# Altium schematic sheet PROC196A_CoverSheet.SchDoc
size 431 x 279 mm; Date: Not shown in title block; ApprovedBy: Not shown in title block; CheckedBy: Not shown in title block; Author: Not shown in title block; CompanyName: Not shown in title block; Engineer: Not shown in title block; Organization: Not shown in title block; Address1: Not shown in title block; Address2: Not shown in title block; Address3: Not shown in title block; Address4: Not shown in title block; DocumentNumber: 1; Revision: Use project parameter SCH_Rev; SheetNumber: 1; SheetTotal: 25; PageSetup: Record=PageOptions¦CenterHorizontal=True¦CenterVertical=True¦PrintScale=1.00¦XCorrection=1.00¦YCorrection=1.00¦PrintKind=0¦BorderSize=5000000¦LeftOffset=0¦BottomOffset=0¦Orientation=2¦PaperLength=1000¦PaperWidth=1000¦Scale=100¦PaperSource=15¦PrintQuality=600¦MediaType=1¦DitherType=10¦PaperKind=Letter¦PrintScaleMode=1
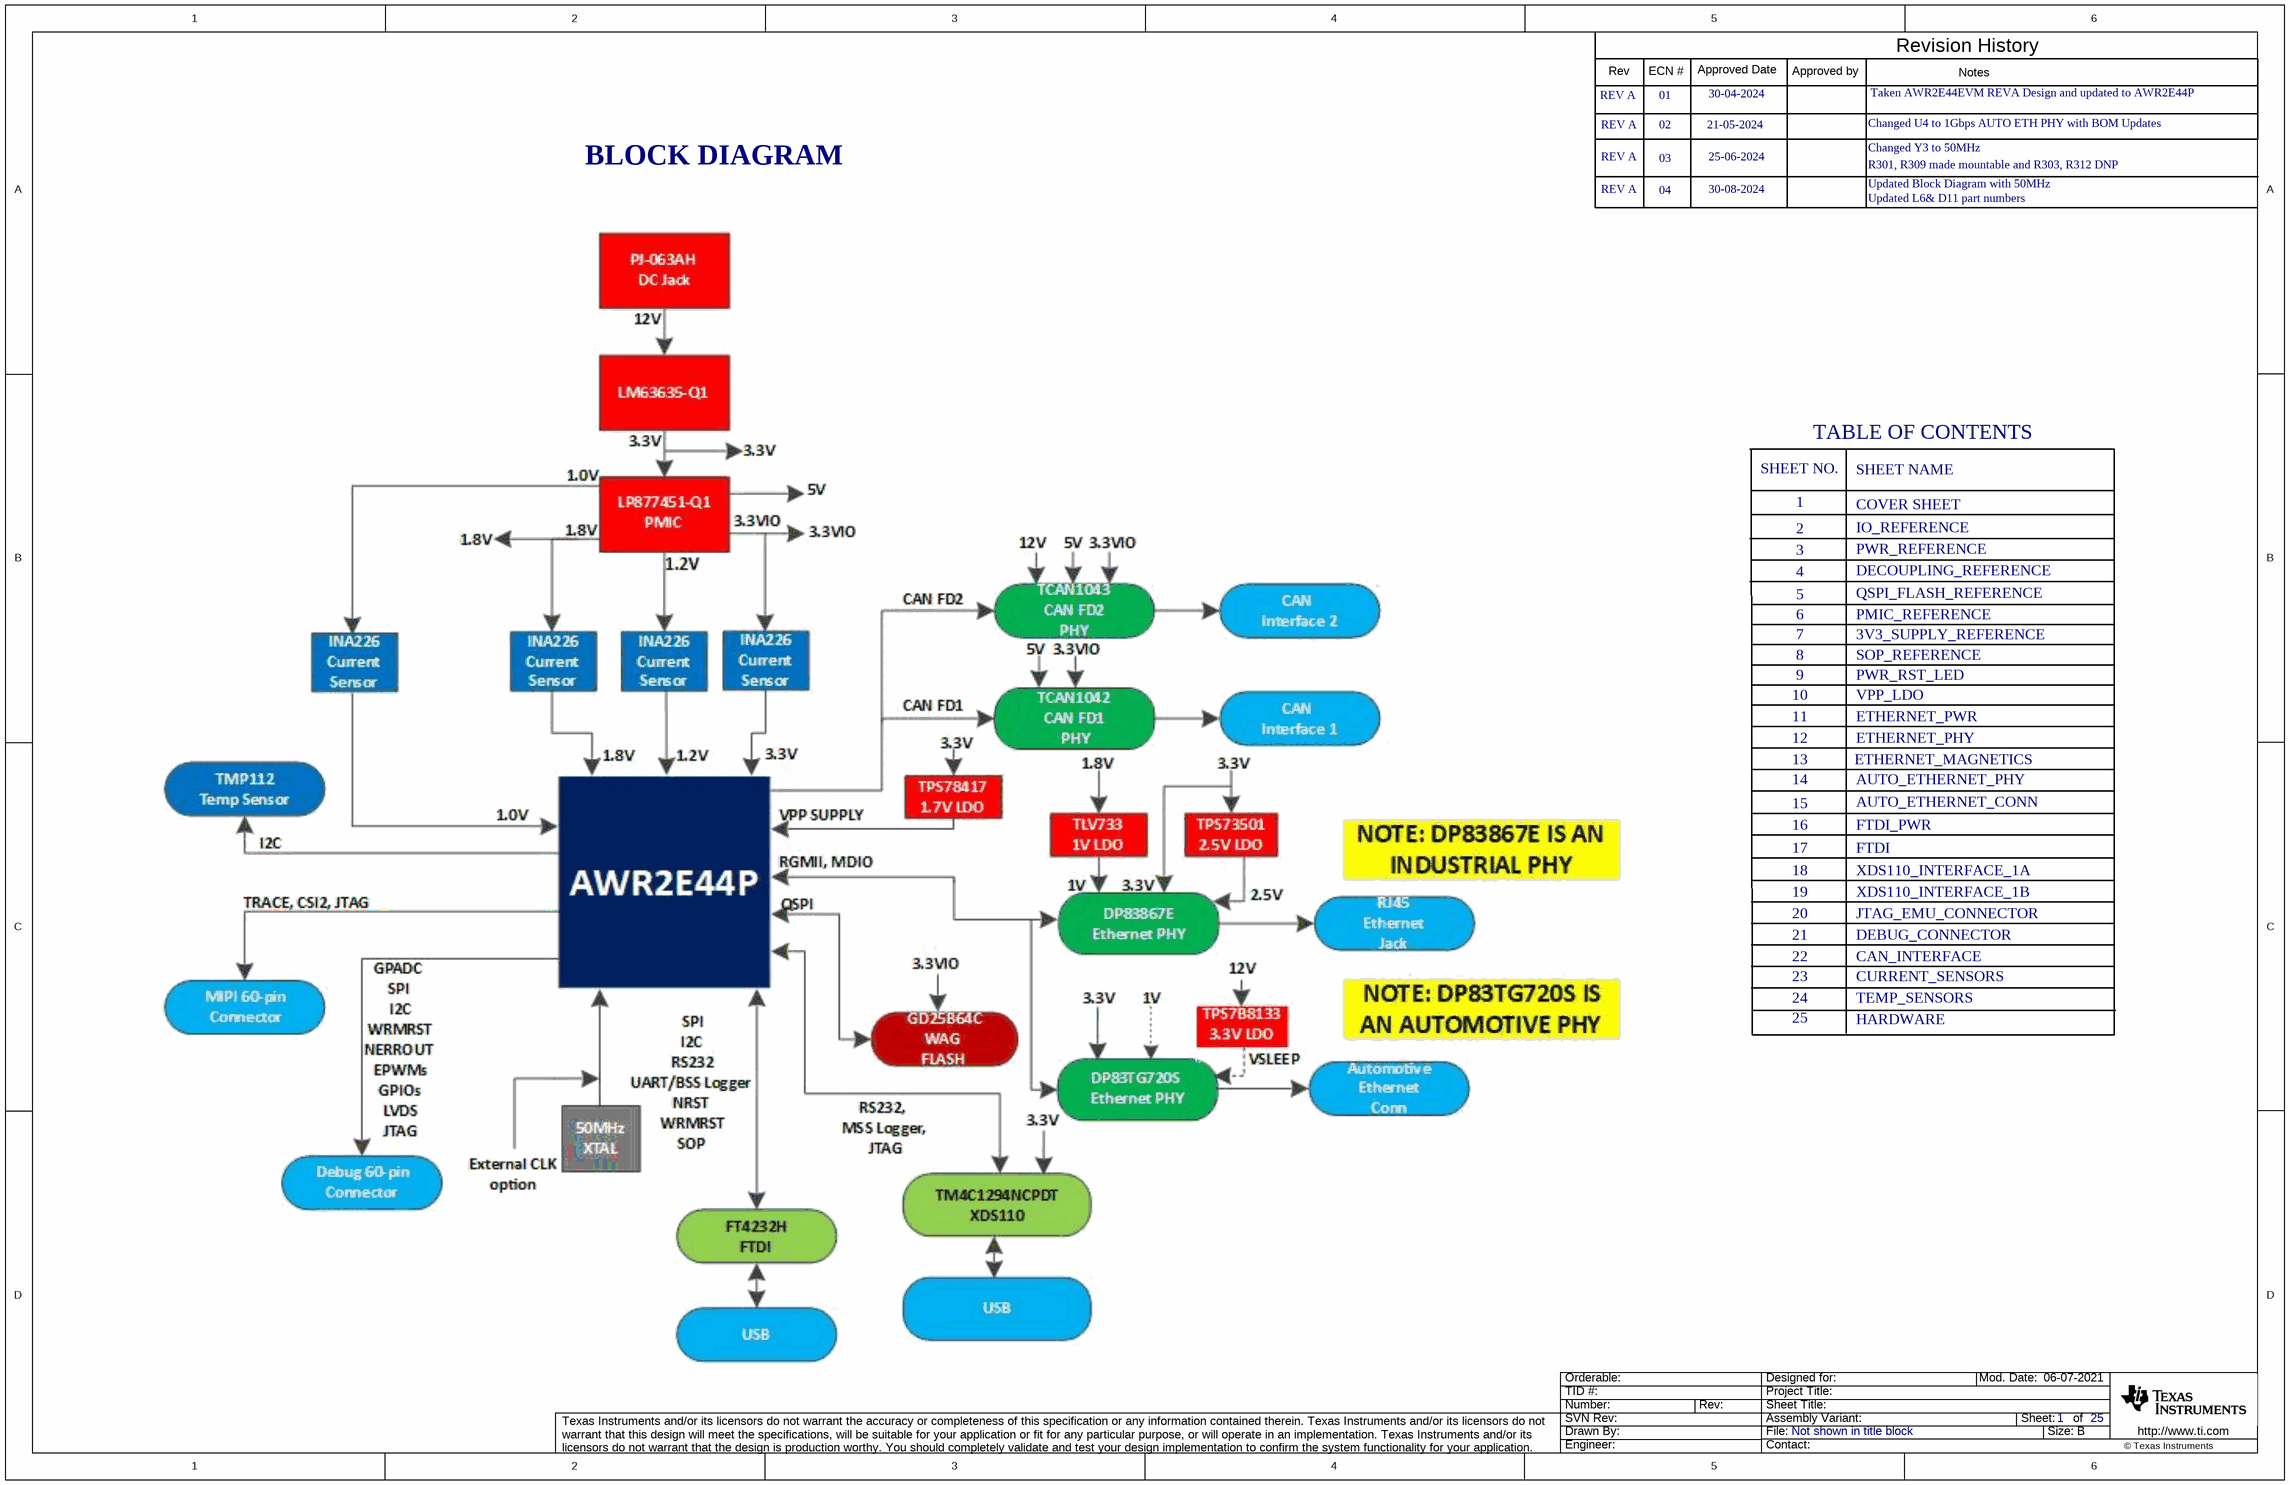
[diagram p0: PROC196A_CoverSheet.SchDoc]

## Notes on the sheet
- REV A
- Rev
- 01
- ECN #
- 30-04-2024
- Approved Date
- Approved by
- Taken AWR2E44EVM REVA Design and updated to AWR2E44P
- Revision History
- Notes
- BLOCK DIAGRAM
- 02
- 03
- 21-05-2024
- 25-06-2024
- Changed U4 to 1Gbps AUTO ETH PHY with BOM Updates
- Changed Y3 to 50MHz
- R301, R309 made mountable and R303, R312 DNP
- 04
- 30-08-2024
- Updated Block Diagram with 50MHz
- Updated L6& D11 part numbers
- SHEET NO.
- TABLE OF CONTENTS
- SHEET NAME
- 1
- 2
- 3
- COVER SHEET
- IO_REFERENCE
- PWR_REFERENCE
- 4
- 5
- 6
- DECOUPLING_REFERENCE
- PMIC_REFERENCE
- QSPI_FLASH_REFERENCE
- 10
- 7
- 8
- 9
- PWR_RST_LED
- SOP_REFERENCE
- VPP_LDO
- 3V3_SUPPLY_REFERENCE
- 11
- 12
- 13
- ETHERNET_MAGNETICS
- ETHERNET_PWR
- ETHERNET_PHY
- 15
- 16
- 14
- FTDI_PWR
- AUTO_ETHERNET_CONN
- AUTO_ETHERNET_PHY
- 17
- 18
- 19
- XDS110_INTERFACE_1B
- XDS110_INTERFACE_1A
- FTDI
- 20
- 21
- 22
- JTAG_EMU_CONNECTOR
- DEBUG_CONNECTOR
- CAN_INTERFACE
- 23
- 24
- 25
- HARDWARE
- CURRENT_SENSORS
- TEMP_SENSORS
